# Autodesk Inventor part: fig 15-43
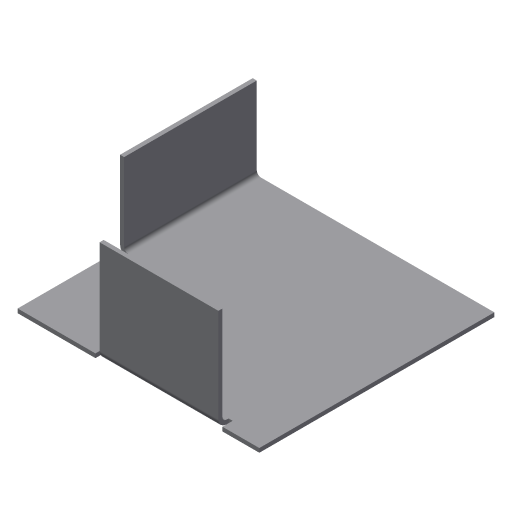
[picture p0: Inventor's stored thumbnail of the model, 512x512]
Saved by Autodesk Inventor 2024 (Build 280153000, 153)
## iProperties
Created: 2005-03
Part Number: fig 15-43
Document SubType Name: Sheet Metal
Designer: CADCIM
Manufacturer: Standard
Standards Organization: Custom
Density: 1 g/cm^3
Sheet Metal Rule: Default
Material: Generic
Appearance: Default
Author: CADCIM
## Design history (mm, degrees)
node "Face1"
  sketch "Sketch1"
    geometry: L1 (-29, -26)-(30, -26); L2 (30, -26)-(30, 31.375); L3 (30, 31.375)-(-29, 31.375); L4 (-29, 31.375)-(-29, -26)
    constraints: 8 end point, 2 parallel, 1 horizontal, 1 perpendicular
node "Flange1"
node "Flange3"
body "Solid1"
face "Plate1" dims "d21" = 1 (= Thickness)
sketch "Sketch2"
  geometry: L1 (25, 0)-(57.375, 0); L2 (57.375, 0)-(57.375, 20); L3 (57.375, 20)-(25, 20); L4 (25, 20)-(25, 0)
  constraints: 8 end point
face "Plate2" dims "d1" = 0, "d2" = 25, "d3" = 1 (= BendReliefWidth), "d5" = 2 (= MinimumRemnant), "d7" = 20, "d8" = 90 deg, "d9" = 1 (= BendRadius), "d21" = 1 (= Thickness)
bend "Bend1" dims "d3" = 1 (= BendReliefWidth), "d4" = 0.5 (= BendReliefDepth), "d5" = 2 (= MinimumRemnant), "d6" = 1 (= BendRadius), "d7" = 20, "d8" = 90 deg, "d9" = 1 (= BendRadius), "d21" = 1 (= Thickness), "SeamGap" = 0.01
sketch "Sketch4"
  geometry: L1 (-39, 0)-(-10, 0); L2 (-10, 0)-(-10, 25); L3 (-10, 25)-(-39, 25); L4 (-39, 25)-(-39, 0)
  constraints: 8 end point
face "Plate4" dims "d21" = 1 (= Thickness), "d22" = 1 (= BendReliefWidth), "d23" = 0.5 (= BendReliefDepth), "d24" = 2 (= MinimumRemnant), "d25" = 1 (= TransitionRadius), "d26" = 20, "d27" = 10, "d28" = 25, "d29" = 90 deg, "d30" = 1 (= BendRadius), "d31" = 4 (= CornerReliefSize), "d32" = 1 (= GapSize), "d33" = 1 (= JacobiRadiusSize), "SeamGap" = 0.01
bend "Bend3" dims "d21" = 1 (= Thickness), "d22" = 1 (= BendReliefWidth), "d23" = 0.5 (= BendReliefDepth), "d24" = 2 (= MinimumRemnant), "d25" = 1 (= TransitionRadius), "d28" = 25, "d29" = 90 deg, "d30" = 1 (= BendRadius), "SeamGap" = 0.01
feature "Corner1" dims "d28" = 25, "d29" = 90 deg, "d31" = 4 (= CornerReliefSize), "d32" = 1 (= GapSize), "d33" = 1 (= JacobiRadiusSize)
other parameters: "Thickness" = 1, "BendRadius" = 1 (= Thickness), "BendReliefWidth" = 1 (= Thickness), "BendReliefDepth" = 0.5 (= 0.5 x Thickness), "CornerReliefSize" = 4 (= 4 x Thickness), "MinimumRemnant" = 2 (= 2 x Thickness), "TransitionRadius" = 1 (= BendRadius), "d0" = 1 (= BendRadius), "JacobiRadiusSize" = 1 (= Thickness), "GapSize" = 1 (= Thickness)
